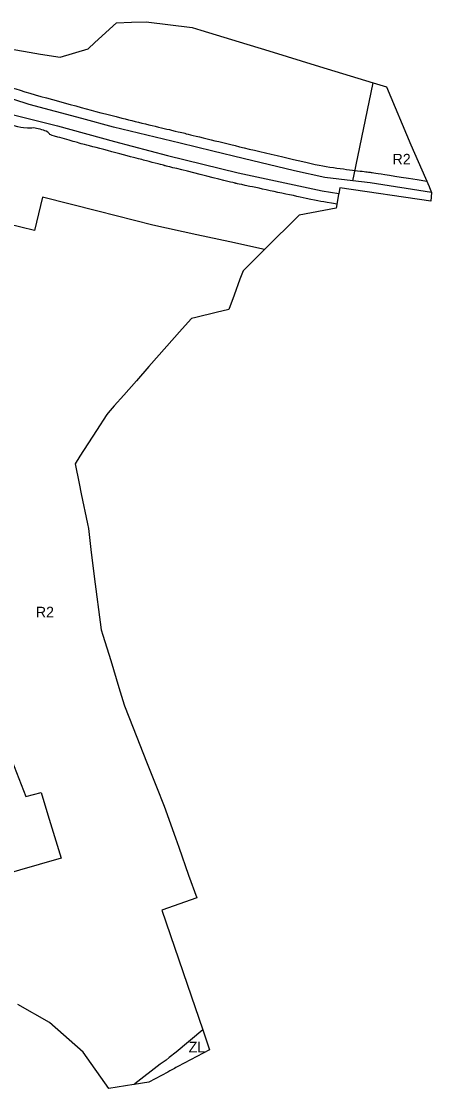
# Model space of a CAD drawing. Extents: x 7413438 to 7416393, y 5541665 to 5544118.
# Drawn here: x 7415721 to 7415953, y 5541870 to 5542473 of the extents above; entities that cross this region are included whole.
import ezdxf

# ---------------------------------------------------------------- set-up
doc = ezdxf.new("R2010")
doc.units = 0
for name, color, linetype in [('linie_rozgraniczajace', 7, 'Continuous'), ('linie_zabudowy_nieprzekraczalne', 7, 'Continuous'), ('oznaczenia_przeznaczen', 7, 'Continuous')]:
    doc.layers.add(name, color=color, linetype=linetype)

msp = doc.modelspace()

# ---------------------------------------------------------------- linework, layer by layer
at = {"layer": 'linie_rozgraniczajace'}
for p, q in [((7415762.98, 5542461.24), (7415775.13, 5542472.52)), ((7415775.13, 5542472.52), (7415783.61, 5542472.76)), ((7415783.61, 5542472.76), (7415792.05, 5542472.99)), ((7415792.05, 5542472.99), (7415817.88, 5542469.8)), ((7415817.88, 5542469.8), (7415822.8, 5542468.29)), ((7415822.8, 5542468.29), (7415844.52, 5542461.66)), ((7415711.91, 5542458.21), (7415732.36, 5542454.81)), ((7415743.43, 5542452.95), (7415759.23, 5542457.74)), ((7415759.23, 5542457.74), (7415762.98, 5542461.24)), ((7415844.52, 5542461.66), (7415861.26, 5542456.54)), ((7415861.26, 5542456.54), (7415889.79, 5542447.78)), ((7415732.36, 5542454.81), (7415743.43, 5542452.95)), ((7415889.79, 5542447.78), (7415920.19, 5542438.53)), ((7415909.42, 5542386.68), (7415920.19, 5542438.53)), ((7415920.19, 5542438.53), (7415927.75, 5542436.23)), ((7415725.92, 5542426.37), (7415705.97, 5542432.65)), ((7415927.75, 5542436.23), (7415941.56, 5542403.56)), ((7415755.68, 5542418.33), (7415725.92, 5542426.37)), ((7415705.9, 5542423.17), (7415741.94, 5542414.25)), ((7415741.94, 5542414.25), (7415774.06, 5542405.44)), ((7415773.53, 5542413.51), (7415755.68, 5542418.33)), ((7415811.16, 5542404.5), (7415773.53, 5542413.51)), ((7415774.06, 5542405.44), (7415804.09, 5542397.54)), ((7415829.62, 5542399.99), (7415811.16, 5542404.5)), ((7415941.56, 5542403.56), (7415951.75, 5542379.97)), ((7415804.09, 5542397.54), (7415843.86, 5542387.63)), ((7415846.81, 5542395.8), (7415829.62, 5542399.99)), ((7415875.77, 5542388.88), (7415846.81, 5542395.8)), ((7415843.86, 5542387.63), (7415891.43, 5542377.48)), ((7415892.93, 5542385.09), (7415875.77, 5542388.88)), ((7415908.69, 5542383.19), (7415892.93, 5542385.09)), ((7415908.69, 5542383.19), (7415909.42, 5542386.68)), ((7415891.43, 5542377.48), (7415900.8, 5542376.01)), ((7415901.34, 5542379.18), (7415900.81, 5542376.02)), ((7415952.75, 5542371.62), (7415901.34, 5542379.18)), ((7415918.45, 5542382.01), (7415908.69, 5542383.19)), ((7415953.22, 5542376.55), (7415918.45, 5542382.01)), ((7415951.75, 5542379.97), (7415951.99, 5542379.42)), ((7415951.99, 5542379.42), (7415953.22, 5542376.55)), ((7415733.43, 5542373.84), (7415728.88, 5542355.05)), ((7415764.66, 5542366.01), (7415733.43, 5542373.84)), ((7415900.7, 5542375.4), (7415899.35, 5542367.79)), ((7415900.8, 5542376.01), (7415900.7, 5542375.41)), ((7415900.7, 5542375.41), (7415900.7, 5542375.4)), ((7415900.81, 5542376.02), (7415900.8, 5542376.01)), ((7415900.8, 5542376.01), (7415900.8, 5542376.01)), ((7415953.22, 5542376.55), (7415952.75, 5542371.62)), ((7415953.22, 5542376.55), (7415953.22, 5542376.55)), ((7415795.8, 5542358.19), (7415764.66, 5542366.01)), ((7415899.35, 5542367.79), (7415878.44, 5542363.8)), ((7415878.44, 5542363.8), (7415858.87, 5542344.39)), ((7415728.88, 5542355.05), (7415713.46, 5542358.78)), ((7415820.56, 5542352.7), (7415795.8, 5542358.19)), ((7415820.59, 5542352.69), (7415820.56, 5542352.7)), ((7415839.16, 5542348.7), (7415820.59, 5542352.69)), ((7415858.87, 5542344.39), (7415839.16, 5542348.7)), ((7415858.87, 5542344.39), (7415851.49, 5542337.06)), ((7415851.49, 5542337.06), (7415846.79, 5542332.38)), ((7415846.79, 5542332.38), (7415844.92, 5542327.6)), ((7415844.92, 5542327.6), (7415841.59, 5542318.57)), ((7415841.59, 5542318.57), (7415838.6, 5542310.55)), ((7415817.57, 5542305.36), (7415812.32, 5542299.52)), ((7415819.98, 5542305.96), (7415817.57, 5542305.36)), ((7415831.46, 5542308.78), (7415819.98, 5542305.96)), ((7415838.6, 5542310.55), (7415831.46, 5542308.78)), ((7415812.32, 5542299.52), (7415793.5, 5542278.16)), ((7415793.5, 5542278.16), (7415786.51, 5542270.23)), ((7415786.41, 5542270.13), (7415779.38, 5542262.15)), ((7415786.51, 5542270.23), (7415786.41, 5542270.13)), ((7415779.38, 5542262.15), (7415773.96, 5542256.03)), ((7415769.81, 5542251.08), (7415763.86, 5542242.05)), ((7415770.51, 5542252.13), (7415769.81, 5542251.08)), ((7415773.96, 5542256.03), (7415770.51, 5542252.13)), ((7415763.86, 5542242.05), (7415754.41, 5542227.61)), ((7415754.41, 5542227.61), (7415751.78, 5542223.35)), ((7415751.78, 5542223.35), (7415754.05, 5542212.13)), ((7415754.05, 5542212.13), (7415755.17, 5542206.39)), ((7415755.17, 5542206.39), (7415758.77, 5542189.3)), ((7415758.77, 5542189.3), (7415759.32, 5542186.69)), ((7415759.32, 5542186.69), (7415760.71, 5542174.79)), ((7415760.71, 5542174.79), (7415762.62, 5542159.53)), ((7415762.62, 5542159.53), (7415766.59, 5542129.49)), ((7415766.59, 5542129.49), (7415767.54, 5542126.43)), ((7415767.54, 5542126.43), (7415771.98, 5542112.05)), ((7415771.98, 5542112.05), (7415776.61, 5542096.84)), ((7415776.61, 5542096.84), (7415779.54, 5542087.1)), ((7415705.21, 5542082.66), (7415724.05, 5542035.34)), ((7415779.54, 5542087.1), (7415779.76, 5542086.55)), ((7415779.76, 5542086.55), (7415784.67, 5542074.05)), ((7415784.67, 5542074.05), (7415792.23, 5542054.96)), ((7415792.23, 5542054.96), (7415797.81, 5542040.83)), ((7415797.81, 5542040.83), (7415802.12, 5542029.89)), ((7415724.05, 5542035.34), (7415732.69, 5542037.58)), ((7415732.69, 5542037.58), (7415736.41, 5542025.02)), ((7415802.12, 5542029.89), (7415808.49, 5542011.89)), ((7415736.41, 5542025.02), (7415743.9, 5542000.49)), ((7415808.49, 5542011.89), (7415810.4, 5542006.6)), ((7415810.4, 5542006.6), (7415815.94, 5541990.81)), ((7415743.9, 5542000.49), (7415680.5, 5541982.3)), ((7415815.94, 5541990.81), (7415820.52, 5541977.98)), ((7415820.52, 5541977.98), (7415800.84, 5541971.02)), ((7415800.84, 5541971.02), (7415815.11, 5541929.19)), ((7415815.11, 5541929.19), (7415823.92, 5541903.39)), ((7415737.4, 5541907.61), (7415719.41, 5541917.74)), ((7415756.37, 5541890.91), (7415737.4, 5541907.61)), ((7415823.92, 5541903.39), (7415808.85, 5541890.92)), ((7415823.92, 5541903.39), (7415827.74, 5541892.22)), ((7415770.94, 5541870.23), (7415756.37, 5541890.91)), ((7415808.85, 5541890.92), (7415805.01, 5541887.74)), ((7415827.74, 5541892.22), (7415809.94, 5541882.72)), ((7415799.85, 5541884.1), (7415785.58, 5541873.02)), ((7415803.32, 5541886.34), (7415799.85, 5541884.1)), ((7415805.01, 5541887.74), (7415803.32, 5541886.34)), ((7415804.18, 5541879.64), (7415793.41, 5541873.9)), ((7415805.33, 5541880.25), (7415804.18, 5541879.64)), ((7415807.92, 5541881.64), (7415805.33, 5541880.25)), ((7415808.77, 5541882.1), (7415807.92, 5541881.64)), ((7415809.94, 5541882.72), (7415808.77, 5541882.1)), ((7415784.92, 5541872.51), (7415770.94, 5541870.23)), ((7415785.25, 5541872.56), (7415784.92, 5541872.51)), ((7415793.41, 5541873.9), (7415785.25, 5541872.56)), ((7415785.58, 5541873.02), (7415785.25, 5541872.56))]:
    msp.add_line(p, q, dxfattribs=at)
at = {"layer": 'linie_zabudowy_nieprzekraczalne'}
for points in [[(7415511.02, 5542661.49), (7415514.82, 5542641.66), (7415518.03, 5542625.4), (7415520.38, 5542613.91), (7415521.88, 5542606.92), (7415522.86, 5542602.65), (7415523.63, 5542599.54), (7415524.21, 5542597.31), (7415524.55, 5542596.01), (7415524.69, 5542595.48), (7415524.73, 5542595.33), (7415524.75, 5542595.24), (7415524.77, 5542595.12), (7415524.79, 5542595.01), (7415524.84, 5542594.68), (7415524.96, 5542593.68), (7415525.22, 5542591.69), (7415525.51, 5542589.37), (7415525.72, 5542587.69), (7415525.81, 5542587), (7415525.83, 5542586.86), (7415525.85, 5542586.73), (7415525.95, 5542586), (7415526.22, 5542584), (7415526.69, 5542580.57), (7415527.28, 5542576.2), (7415527.92, 5542571.51), (7415528.49, 5542567.31), (7415528.88, 5542564.47), (7415529.12, 5542562.61), (7415529.54, 5542559.36), (7415530.37, 5542552.75), (7415531.4, 5542544.63), (7415532.19, 5542538.42), (7415532.57, 5542535.35), (7415532.87, 5542532.85), (7415533.39, 5542528.45), (7415534.03, 5542522.94), (7415534.53, 5542518.68), (7415534.74, 5542516.81), (7415534.79, 5542516.39), (7415534.8, 5542516.31), (7415534.81, 5542516.2), (7415534.81, 5542516.09), (7415534.82, 5542515.91), (7415534.82, 5542515.42), (7415534.82, 5542514.39), (7415534.82, 5542513.09), (7415534.82, 5542512.04), (7415534.82, 5542511.55), (7415534.81, 5542511.38), (7415534.81, 5542511.28), (7415534.8, 5542511.17), (7415534.79, 5542511.06), (7415534.72, 5542510.45), (7415534.35, 5542507.63), (7415533.49, 5542500.98), (7415532.47, 5542491.97), (7415531.63, 5542477.4), (7415559.07, 5542470.57), (7415584.68, 5542465.35), (7415619.26, 5542458.32), (7415619.26, 5542458.32), (7415651.48, 5542451.74), (7415651.6, 5542451.72), (7415651.67, 5542451.7), (7415702.44, 5542439.32), (7415707.66, 5542438.37), (7415707.77, 5542438.33), (7415727.6, 5542432.09), (7415757.24, 5542424.08), (7415775.01, 5542419.29), (7415812.56, 5542410.29), (7415812.58, 5542410.29), (7415831.04, 5542405.78), (7415848.22, 5542401.59), (7415877.11, 5542394.69), (7415893.94, 5542390.97), (7415909.41, 5542389.1), (7415919.17, 5542387.92), (7415919.38, 5542387.89), (7415950.44, 5542383.02)], [(7415899.76, 5542370.06), (7415890.5, 5542371.51), (7415890.18, 5542371.57), (7415842.61, 5542381.72), (7415842.54, 5542381.73), (7415842.41, 5542381.77), (7415802.64, 5542391.68), (7415802.56, 5542391.7), (7415799.82, 5542392.42), (7415790.68, 5542394.82), (7415790.68, 5542394.82), (7415772.53, 5542399.6), (7415754.12, 5542404.43), (7415753.97, 5542404.47), (7415740.38, 5542408.42), (7415736.95, 5542409.26), (7415737.33, 5542411.02), (7415726.72, 5542413.79), (7415726.34, 5542411.89), (7415704.45, 5542417.31), (7415694.73, 5542419.72), (7415670.48, 5542425.71), (7415651.75, 5542430.33), (7415649.18, 5542430.32), (7415618.58, 5542436.91), (7415611.16, 5542438.51), (7415611.15, 5542438.51), (7415606.13, 5542439.6), (7415585.02, 5542444.04), (7415584.99, 5542444.05), (7415570.36, 5542447.23), (7415564.82, 5542448.43), (7415564.92, 5542449.35), (7415557.02, 5542450.59), (7415551.9, 5542451.66), (7415551.7, 5542451.18), (7415543.32, 5542453.53), (7415530.6, 5542457.08), (7415530.59, 5542457.08), (7415527.99, 5542457.81), (7415524.72, 5542458.51), (7415520.86, 5542458.61), (7415520.47, 5542458.63), (7415520.11, 5542458.67), (7415506.46, 5542460.74), (7415493.13, 5542462.73), (7415493.09, 5542462.74), (7415492.77, 5542462.8), (7415490.79, 5542463.22)]]:
    msp.add_open_spline(points, degree=3, dxfattribs=at)

# ---------------------------------------------------------------- texts
at = {"layer": 'oznaczenia_przeznaczen'}
for s, p in [('R2', (7415931.13, 5542392.4)), ('R2', (7415729.63, 5542136.5)), ('ZL', (7415815.96, 5541890.74))]:
    msp.add_text(s, height=6, dxfattribs=at).set_placement(p)

doc.saveas('drawing.dxf')
